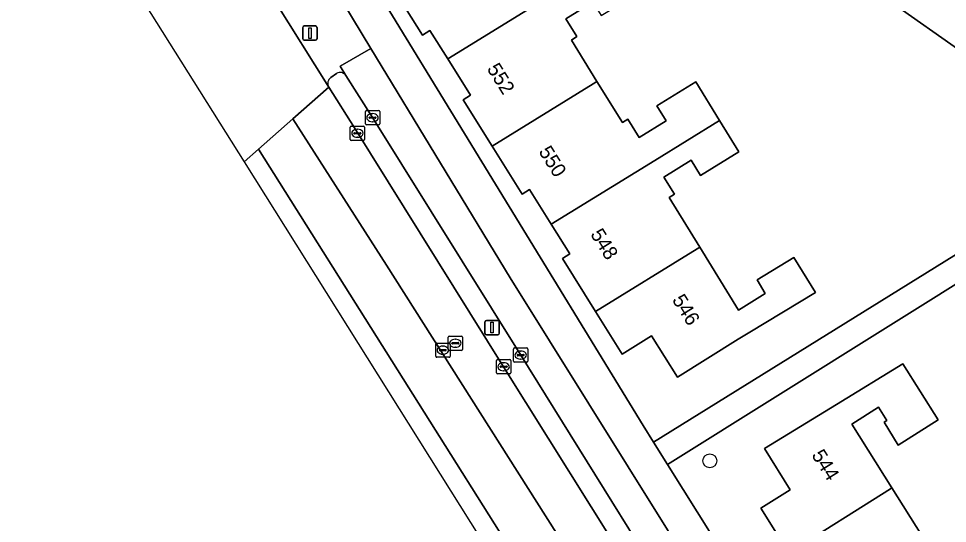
# Model space of a CAD drawing. Extents: x 159664 to 160323, y 385312 to 386115.
# Drawn here: x 159664.3 to 159729.1, y 385837.6 to 385872.8 of the extents above; entities that cross this region are included whole.
import ezdxf

# ---------------------------------------------------------------- set-up
doc = ezdxf.new("R2010")
doc.units = 0
for name, color, linetype in [('IMGEO_Berm_open', 7, 'Continuous'), ('IMGEO_Boom', 7, 'Continuous'), ('IMGEO_Erf', 7, 'Continuous'), ('IMGEO_Fietspad_gesloten', 7, 'Continuous'), ('IMGEO_Fietspad_open', 7, 'Continuous'), ('IMGEO_Kolk', 7, 'Continuous'), ('IMGEO_Lichtmast', 7, 'Continuous'), ('IMGEO_Pand', 7, 'Continuous'), ('IMGEO_Pand_nummerreeks', 7, 'Continuous'), ('IMGEO_Rijbaan_regionaal_gesloten', 7, 'Continuous'), ('IMGEO_Rioolput', 7, 'Continuous'), ('IMGEO_Verkeersregelinstallatiepaal', 7, 'Continuous'), ('IMGEO_Voetpad_open', 7, 'Continuous')]:
    doc.layers.add(name, color=color, linetype=linetype)

msp = doc.modelspace()

# ---------------------------------------------------------------- linework, layer by layer
at = {"layer": 'IMGEO_Berm_open'}
for points in [[(159686.512, 385869.015), (159686.109, 385868.721)], [(159699.356, 385849.333), (159689.016, 385865.92), (159687.159, 385868.865)], [(159685.962, 385868.059), (159687.762, 385865.202), (159698.166, 385848.523), (159707.398, 385833.746), (159719.9, 385813.65), (159720.286, 385813.027), (159720.44, 385812.85)], [(159721.514, 385813.73), (159720.566, 385815.282), (159708.631, 385834.436), (159699.356, 385849.333)]]:
    msp.add_lwpolyline(points, dxfattribs=at)
for centre, radius, start, end in [((159686.39, 385868.311), 0.497, 124.44432, 210.5164), ((159686.751, 385868.576), 0.5, 35.31305, 118.58133)]:
    msp.add_arc(centre, radius, start, end, dxfattribs=at)
at = {"layer": 'IMGEO_Boom'}
msp.add_circle((159712.557, 385841.947), 0.489, dxfattribs=at)
at = {"layer": 'IMGEO_Erf'}
for points in [[(159736.353, 385866.149), (159719.037, 385878.37)], [(159687.283, 385878.163), (159707.902, 385844.411), (159708.629, 385843.25), (159739.153, 385862.198)], [(159711.57, 385868.416), (159713.23, 385865.722), (159714.585, 385863.522), (159711.909, 385861.874), (159711.251, 385862.941), (159709.352, 385861.772), (159710.092, 385860.572), (159709.716, 385860.34), (159711.853, 385856.871), (159714.556, 385852.483), (159716.432, 385853.639), (159715.851, 385854.581), (159718.41, 385856.158), (159719.924, 385853.7), (159715.347, 385850.939), (159714.539, 385850.435), (159710.298, 385847.786), (159708.488, 385850.684), (159706.449, 385849.41), (159704.586, 385852.389), (159702.27, 385856.091), (159702.78, 385856.41), (159701.485, 385858.479), (159699.969, 385860.903), (159699.461, 385860.585), (159697.364, 385863.939), (159695.347, 385867.165), (159695.856, 385867.483), (159694.263, 385870.029), (159693.024, 385872.01), (159692.515, 385871.692), (159690.141, 385875.488)], [(159704.398, 385873.991), (159702.511, 385872.828), (159703.28, 385871.58), (159702.898, 385871.344), (159704.68, 385868.451), (159706.455, 385865.57), (159706.839, 385865.807), (159707.624, 385864.532), (159709.517, 385865.698), (159708.868, 385866.751), (159711.57, 385868.416)], [(159718.061, 385835.526), (159716.118, 385838.631), (159718.175, 385839.916), (159716.363, 385842.815), (159721.394, 385845.894), (159726.034, 385848.734), (159728.503, 385844.802), (159725.712, 385843.049), (159724.715, 385844.637), (159724.924, 385844.769), (159724.34, 385845.699), (159722.462, 385844.52), (159725.268, 385840.05), (159727.349, 385836.736)]]:
    msp.add_lwpolyline(points, dxfattribs=at)
msp.add_lwpolyline([(159749.78, 385845.505), (159747.52, 385845.517), (159747.246, 385845.967), (159748.353, 385847.97), (159740.221, 385860.856), (159709.605, 385841.691), (159725.533, 385816.246), (159727.547, 385813.028), (159757.404, 385831.429), (159757.978, 385832.141), (159757.978, 385832.633)], close=True, dxfattribs=at)
at = {"layer": 'IMGEO_Fietspad_gesloten'}
msp.add_lwpolyline([(159689.016, 385865.92), (159699.356, 385849.333), (159708.631, 385834.436), (159720.566, 385815.282), (159721.514, 385813.73), (159726.241, 385806.163), (159746.799, 385773.289), (159761.349, 385750), (159769.568, 385736.844), (159790.48, 385703.378), (159792.384, 385704.563), (159772.652, 385736.21), (159767.476, 385744.488), (159764.031, 385750), (159753.712, 385766.513), (159748.937, 385774.15), (159728.287, 385807.194), (159723.506, 385814.826), (159723.438, 385814.935), (159698.624, 385854.738), (159688.899, 385870.747), (159686.756, 385869.506), (159687.159, 385868.865)], close=True, dxfattribs=at)
at = {"layer": 'IMGEO_Fietspad_open'}
for points in [[(159687.159, 385868.865), (159686.756, 385869.506), (159688.899, 385870.747), (159685.047, 385877.122)], [(159681.196, 385875.993), (159682.169, 385874.114), (159685.962, 385868.059)], [(159686.109, 385868.721), (159686.512, 385869.015)]]:
    msp.add_lwpolyline(points, dxfattribs=at)
for centre, radius, start, end in [((159686.39, 385868.311), 0.497, 124.44432, 210.5164), ((159686.751, 385868.576), 0.5, 35.31305, 118.58133)]:
    msp.add_arc(centre, radius, start, end, dxfattribs=at)
at = {"layer": 'IMGEO_Kolk'}
for p, q in [((159688.514, 385865.493), (159688.514, 385866.345)), ((159688.589, 385866.419), (159689.441, 385866.419)), ((159688.816, 385865.962), (159689.214, 385865.962)), ((159689.002, 385866.199), (159689.027, 385866.199)), ((159689.515, 385866.345), (159689.515, 385865.493)), ((159687.536, 385865.328), (159688.388, 385865.328)), ((159689.441, 385865.419), (159688.589, 385865.419)), ((159688.773, 385865.913), (159688.773, 385865.925)), ((159689.211, 385865.876), (159688.813, 385865.876)), ((159689.025, 385865.639), (159689, 385865.639)), ((159689.257, 385865.925), (159689.257, 385865.913)), ((159687.461, 385864.402), (159687.461, 385865.254)), ((159687.72, 385864.822), (159687.72, 385864.834)), ((159688.158, 385864.785), (159687.76, 385864.785)), ((159687.763, 385864.871), (159688.161, 385864.871)), ((159687.949, 385865.108), (159687.974, 385865.108)), ((159688.204, 385864.834), (159688.204, 385864.822)), ((159688.462, 385865.254), (159688.462, 385864.402)), ((159688.388, 385864.328), (159687.536, 385864.328)), ((159687.972, 385864.548), (159687.947, 385864.548)), ((159698.854, 385848.907), (159698.854, 385849.759)), ((159698.929, 385849.833), (159699.781, 385849.833)), ((159699.855, 385849.759), (159699.855, 385848.907)), ((159699.113, 385849.327), (159699.113, 385849.339)), ((159699.551, 385849.29), (159699.153, 385849.29)), ((159699.156, 385849.376), (159699.554, 385849.376)), ((159699.342, 385849.613), (159699.367, 385849.613)), ((159699.597, 385849.339), (159699.597, 385849.327)), ((159697.664, 385848.096), (159697.664, 385848.948)), ((159697.739, 385849.022), (159698.591, 385849.022)), ((159697.923, 385848.516), (159697.923, 385848.528)), ((159698.361, 385848.479), (159697.963, 385848.479)), ((159697.966, 385848.565), (159698.364, 385848.565)), ((159698.152, 385848.802), (159698.177, 385848.802)), ((159698.407, 385848.528), (159698.407, 385848.516)), ((159698.665, 385848.948), (159698.665, 385848.096)), ((159699.781, 385848.833), (159698.929, 385848.833)), ((159699.365, 385849.053), (159699.34, 385849.053)), ((159698.591, 385848.022), (159697.739, 385848.022)), ((159698.175, 385848.242), (159698.15, 385848.242))]:
    msp.add_line(p, q, dxfattribs=at)
for points in [[(159688.514, 385865.493), (159688.514, 385866.345)], [(159688.589, 385866.419), (159689.441, 385866.419)], [(159689.515, 385866.345), (159689.515, 385865.493)], [(159687.536, 385865.328), (159688.388, 385865.328)], [(159689.441, 385865.419), (159688.589, 385865.419)], [(159687.461, 385864.402), (159687.461, 385865.254)], [(159688.462, 385865.254), (159688.462, 385864.402)], [(159688.388, 385864.328), (159687.536, 385864.328)], [(159698.854, 385848.907), (159698.854, 385849.759)], [(159698.929, 385849.833), (159699.781, 385849.833)], [(159699.855, 385849.759), (159699.855, 385848.907)], [(159697.664, 385848.096), (159697.664, 385848.948)], [(159697.739, 385849.022), (159698.591, 385849.022)], [(159698.665, 385848.948), (159698.665, 385848.096)], [(159699.781, 385848.833), (159698.929, 385848.833)], [(159698.591, 385848.022), (159697.739, 385848.022)]]:
    msp.add_lwpolyline(points, dxfattribs=at)
for centre, radius, start, end in [((159688.591, 385866.343), 0.0765, 91.55205, 178.44795), ((159688.591, 385866.343), 0.0765, 91.55205, 178.44795), ((159688.813, 385865.922), 0.0403, 85.87752, 175.75265), ((159689.218, 385865.924), 0.0386, 1.73085, 96.63898), ((159689.439, 385866.343), 0.0765, 1.55205, 88.44795), ((159689.439, 385866.343), 0.0765, 1.55205, 88.44795), ((159687.538, 385865.252), 0.0765, 91.55205, 178.44795), ((159687.538, 385865.252), 0.0765, 91.55205, 178.44795), ((159688.386, 385865.252), 0.0765, 1.55205, 88.44795), ((159688.386, 385865.252), 0.0765, 1.55205, 88.44795), ((159688.591, 385865.495), 0.0765, 181.55205, 268.44795), ((159688.591, 385865.495), 0.0765, 181.55205, 268.44795), ((159688.81, 385865.912), 0.0366, 178.93798, 274.71019), ((159689.214, 385865.919), 0.043, 264.86636, 352.45326), ((159689.439, 385865.495), 0.0765, 271.55205, 358.44795), ((159689.439, 385865.495), 0.0765, 271.55205, 358.44795), ((159687.76, 385864.831), 0.0403, 85.87752, 175.75265), ((159687.757, 385864.821), 0.0366, 178.93798, 274.71019), ((159688.161, 385864.828), 0.043, 264.86636, 352.45326), ((159688.165, 385864.833), 0.0386, 1.73085, 96.63898), ((159687.538, 385864.404), 0.0765, 181.55205, 268.44795), ((159687.538, 385864.404), 0.0765, 181.55205, 268.44795), ((159688.386, 385864.404), 0.0765, 271.55205, 358.44795), ((159688.386, 385864.404), 0.0765, 271.55205, 358.44795), ((159698.931, 385849.757), 0.0765, 91.55205, 178.44795), ((159698.931, 385849.757), 0.0765, 91.55205, 178.44795), ((159699.779, 385849.757), 0.0765, 1.55205, 88.44795), ((159699.779, 385849.757), 0.0765, 1.55205, 88.44795), ((159699.153, 385849.336), 0.0403, 85.87752, 175.75265), ((159699.15, 385849.326), 0.0366, 178.93798, 274.71019), ((159699.554, 385849.333), 0.043, 264.86636, 352.45326), ((159699.558, 385849.338), 0.0386, 1.73085, 96.63898), ((159697.741, 385848.946), 0.0765, 91.55205, 178.44795), ((159697.741, 385848.946), 0.0765, 91.55205, 178.44795), ((159697.963, 385848.525), 0.0403, 85.87752, 175.75265), ((159697.96, 385848.515), 0.0366, 178.93798, 274.71019), ((159698.364, 385848.522), 0.043, 264.86636, 352.45326), ((159698.368, 385848.527), 0.0386, 1.73085, 96.63898), ((159698.589, 385848.946), 0.0765, 1.55205, 88.44795), ((159698.589, 385848.946), 0.0765, 1.55205, 88.44795), ((159698.931, 385848.909), 0.0765, 181.55205, 268.44795), ((159698.931, 385848.909), 0.0765, 181.55205, 268.44795), ((159699.779, 385848.909), 0.0765, 271.55205, 358.44795), ((159699.779, 385848.909), 0.0765, 271.55205, 358.44795), ((159697.741, 385848.098), 0.0765, 181.55205, 268.44795), ((159697.741, 385848.098), 0.0765, 181.55205, 268.44795), ((159698.589, 385848.098), 0.0765, 271.55205, 358.44795), ((159698.589, 385848.098), 0.0765, 271.55205, 358.44795)]:
    msp.add_arc(centre, radius, start, end, dxfattribs=at)
for centre, major_axis, ratio, start_param, end_param in [((159689.001, 385865.919), (-0.387, 0.002), 0.722429, 4.712389, 7.853982), ((159689.026, 385865.919), (-0.39, 0.002), 0.717154, 1.570796, 4.712389), ((159687.948, 385864.828), (-0.387, 0.002), 0.722429, 4.712389, 7.853982), ((159687.973, 385864.828), (-0.39, 0.002), 0.717154, 1.570796, 4.712389), ((159699.341, 385849.333), (-0.387, 0.002), 0.722429, 4.712389, 7.853982), ((159699.366, 385849.333), (-0.39, 0.002), 0.717154, 1.570796, 4.712389), ((159698.151, 385848.522), (-0.387, 0.002), 0.722429, 4.712389, 7.853982), ((159698.176, 385848.522), (-0.39, 0.002), 0.717154, 1.570796, 4.712389)]:
    msp.add_ellipse(centre, major_axis=major_axis, ratio=ratio, start_param=start_param, end_param=end_param, dxfattribs=at)
at = {"layer": 'IMGEO_Lichtmast'}
for p, q in [((159696.963, 385851.753), (159697.753, 385851.753)), ((159697.753, 385851.753), (159696.963, 385851.753)), ((159696.863, 385850.853), (159696.863, 385851.653)), ((159696.863, 385851.653), (159696.863, 385850.853)), ((159697.853, 385851.653), (159697.853, 385850.853)), ((159697.853, 385850.853), (159697.853, 385851.653)), ((159697.753, 385850.753), (159696.963, 385850.753)), ((159696.963, 385850.753), (159697.753, 385850.753))]:
    msp.add_line(p, q, dxfattribs=at)
msp.add_lwpolyline([(159697.283, 385851.628), (159697.433, 385851.628), (159697.433, 385850.878), (159697.283, 385850.878), (159697.283, 385851.628)], dxfattribs=at)
for centre, start, end in [((159696.963, 385851.653), 90, 180), ((159696.963, 385851.653), 90, 180), ((159697.753, 385851.653), 0, 90), ((159697.753, 385851.653), 360, 90), ((159696.963, 385850.853), 180, 270), ((159696.963, 385850.853), 180, 270), ((159697.753, 385850.853), 270, 0), ((159697.753, 385850.853), 270, 0)]:
    msp.add_arc(centre, 0.1, start, end, dxfattribs=at)
at = {"layer": 'IMGEO_Pand'}
for points in [[(159701.957, 385877.871), (159702.633, 385876.773), (159700.782, 385875.633), (159700.016, 385876.876), (159699.596, 385876.618), (159697.497, 385880.025), (159697.209, 385879.847), (159690.141, 385875.488), (159692.515, 385871.692), (159693.024, 385872.01), (159694.263, 385870.029), (159701.352, 385874.4), (159706.083, 385877.318), (159704.701, 385879.561)], [(159702.898, 385871.344), (159703.28, 385871.58), (159702.511, 385872.828), (159704.398, 385873.991), (159704.981, 385873.046), (159707.688, 385874.713), (159706.29, 385876.983), (159706.083, 385877.318), (159701.352, 385874.4), (159694.263, 385870.029), (159695.856, 385867.483), (159695.347, 385867.165), (159697.364, 385863.939), (159704.411, 385868.285), (159704.68, 385868.451)], [(159713.23, 385865.722), (159711.57, 385868.416), (159708.868, 385866.751), (159709.517, 385865.698), (159707.624, 385864.532), (159706.839, 385865.807), (159706.455, 385865.57), (159704.68, 385868.451), (159704.411, 385868.285), (159697.364, 385863.939), (159699.461, 385860.585), (159699.969, 385860.903), (159701.485, 385858.479), (159708.714, 385862.937)], [(159708.714, 385862.937), (159701.485, 385858.479), (159702.78, 385856.41), (159702.27, 385856.091), (159704.586, 385852.389), (159711.684, 385856.767), (159711.853, 385856.871), (159709.716, 385860.34), (159710.092, 385860.572), (159709.352, 385861.772), (159711.251, 385862.941), (159711.909, 385861.874), (159714.585, 385863.522), (159713.23, 385865.722)], [(159711.684, 385856.767), (159704.586, 385852.389), (159706.449, 385849.41), (159708.488, 385850.684), (159710.298, 385847.786), (159714.539, 385850.435), (159715.347, 385850.939), (159719.924, 385853.7), (159718.41, 385856.158), (159715.851, 385854.581), (159716.432, 385853.639), (159714.556, 385852.483), (159711.853, 385856.871)], [(159716.363, 385842.815), (159718.175, 385839.916), (159716.118, 385838.631), (159718.061, 385835.526), (159725.165, 385839.985), (159725.268, 385840.05), (159722.462, 385844.52), (159724.34, 385845.699), (159724.924, 385844.769), (159724.715, 385844.637), (159725.712, 385843.049), (159728.503, 385844.802), (159726.034, 385848.734), (159721.394, 385845.894)], [(159725.165, 385839.985), (159718.061, 385835.526), (159720.309, 385831.935), (159720.818, 385832.253), (159722.25, 385829.965), (159729.463, 385834.492), (159733.573, 385837.072), (159732.097, 385839.423), (159729.78, 385837.969), (159730.423, 385836.946), (159728.525, 385835.755), (159727.751, 385836.987), (159727.349, 385836.736), (159725.268, 385840.05)]]:
    msp.add_lwpolyline(points, close=True, dxfattribs=at)
at = {"layer": 'IMGEO_Rijbaan_regionaal_gesloten'}
for points in [[(159673.153, 385891.368), (159672.265, 385892.74), (159664.311, 385887.909), (159680.046, 385862.823)], [(159680.046, 385862.823), (159681.056, 385863.717), (159683.457, 385865.842), (159685.962, 385868.059), (159682.169, 385874.114), (159681.196, 385875.993), (159680.604, 385877.808), (159680.45, 385878.908), (159674.897, 385888.863), (159674.772, 385888.772)], [(159704.448, 385832.81), (159689.98, 385855.614), (159683.457, 385865.842), (159681.056, 385863.717), (159700.472, 385832.883)]]:
    msp.add_lwpolyline(points, dxfattribs=at)
for points in [[(159707.398, 385833.746), (159698.166, 385848.523), (159687.762, 385865.202), (159685.962, 385868.059), (159683.457, 385865.842), (159689.98, 385855.614), (159704.448, 385832.81), (159718.81, 385810.264), (159721.888, 385803.885), (159722.743, 385802.489), (159722.776, 385802.519), (159722.812, 385802.546), (159722.85, 385802.57), (159722.891, 385802.59), (159722.932, 385802.607), (159722.975, 385802.619), (159723.019, 385802.628), (159723.064, 385802.633), (159723.109, 385802.634), (159723.154, 385802.631), (159720.687, 385811.648), (159720.121, 385812.906), (159720.286, 385813.027), (159719.9, 385813.65)], [(159722.474, 385795.185), (159718.071, 385804.138), (159716.049, 385808.25), (159711.375, 385815.569), (159700.472, 385832.883), (159681.056, 385863.717), (159680.046, 385862.823)]]:
    msp.add_lwpolyline(points, close=True, dxfattribs=at)
at = {"layer": 'IMGEO_Rioolput'}
for p, q in [((159694.294, 385849.735), (159694.294, 385850.587)), ((159694.369, 385850.661), (159695.221, 385850.661)), ((159694.782, 385850.441), (159694.807, 385850.441)), ((159695.295, 385850.587), (159695.295, 385849.735)), ((159693.424, 385849.252), (159693.424, 385850.104)), ((159693.499, 385850.178), (159694.351, 385850.178)), ((159693.912, 385849.958), (159693.937, 385849.958)), ((159694.425, 385850.104), (159694.425, 385849.252)), ((159694.553, 385850.155), (159694.553, 385850.167)), ((159694.991, 385850.118), (159694.593, 385850.118)), ((159694.596, 385850.204), (159694.994, 385850.204)), ((159694.805, 385849.881), (159694.78, 385849.881)), ((159695.037, 385850.167), (159695.037, 385850.155)), ((159694.351, 385849.178), (159693.499, 385849.178)), ((159693.683, 385849.672), (159693.683, 385849.684)), ((159694.121, 385849.635), (159693.723, 385849.635)), ((159693.726, 385849.721), (159694.124, 385849.721)), ((159693.935, 385849.398), (159693.91, 385849.398)), ((159694.167, 385849.684), (159694.167, 385849.672)), ((159695.221, 385849.661), (159694.369, 385849.661))]:
    msp.add_line(p, q, dxfattribs=at)
for points in [[(159694.294, 385849.735), (159694.294, 385850.587)], [(159694.369, 385850.661), (159695.221, 385850.661)], [(159695.295, 385850.587), (159695.295, 385849.735)], [(159693.424, 385849.252), (159693.424, 385850.104)], [(159693.499, 385850.178), (159694.351, 385850.178)], [(159694.425, 385850.104), (159694.425, 385849.252)], [(159694.351, 385849.178), (159693.499, 385849.178)], [(159695.221, 385849.661), (159694.369, 385849.661)]]:
    msp.add_lwpolyline(points, dxfattribs=at)
for centre, radius, start, end in [((159694.371, 385850.585), 0.0765, 91.55205, 178.44795), ((159694.371, 385850.585), 0.0765, 91.55205, 178.44795), ((159695.219, 385850.585), 0.0765, 1.55205, 88.44795), ((159695.219, 385850.585), 0.0765, 1.55205, 88.44795), ((159693.501, 385850.102), 0.0765, 91.55205, 178.44795), ((159693.501, 385850.102), 0.0765, 91.55205, 178.44795), ((159694.349, 385850.102), 0.0765, 1.55205, 88.44795), ((159694.349, 385850.102), 0.0765, 1.55205, 88.44795), ((159694.593, 385850.164), 0.0403, 85.87752, 175.75265), ((159694.59, 385850.154), 0.0366, 178.93798, 274.71019), ((159694.994, 385850.161), 0.043, 264.86636, 352.45326), ((159694.998, 385850.166), 0.0386, 1.73085, 96.63898), ((159693.501, 385849.254), 0.0765, 181.55205, 268.44795), ((159693.501, 385849.254), 0.0765, 181.55205, 268.44795), ((159693.723, 385849.681), 0.0403, 85.87752, 175.75265), ((159693.72, 385849.671), 0.0366, 178.93798, 274.71019), ((159694.124, 385849.678), 0.043, 264.86636, 352.45326), ((159694.128, 385849.683), 0.0386, 1.73085, 96.63898), ((159694.371, 385849.737), 0.0765, 181.55205, 268.44795), ((159694.371, 385849.737), 0.0765, 181.55205, 268.44795), ((159694.349, 385849.254), 0.0765, 271.55205, 358.44795), ((159694.349, 385849.254), 0.0765, 271.55205, 358.44795), ((159695.219, 385849.737), 0.0765, 271.55205, 358.44795), ((159695.219, 385849.737), 0.0765, 271.55205, 358.44795)]:
    msp.add_arc(centre, radius, start, end, dxfattribs=at)
for centre, major_axis, ratio, start_param, end_param in [((159694.781, 385850.161), (-0.387, 0.002), 0.722429, 4.712389, 7.853982), ((159694.806, 385850.161), (-0.39, 0.002), 0.717154, 1.570796, 4.712389), ((159693.911, 385849.678), (-0.387, 0.002), 0.722429, 4.712389, 7.853982), ((159693.936, 385849.678), (-0.39, 0.002), 0.717154, 1.570796, 4.712389)]:
    msp.add_ellipse(centre, major_axis=major_axis, ratio=ratio, start_param=start_param, end_param=end_param, dxfattribs=at)
at = {"layer": 'IMGEO_Verkeersregelinstallatiepaal'}
for p, q in [((159684.152, 385871.425), (159684.152, 385872.225)), ((159684.152, 385872.225), (159684.152, 385871.425)), ((159684.252, 385872.325), (159685.042, 385872.325)), ((159685.042, 385872.325), (159684.252, 385872.325)), ((159685.142, 385872.225), (159685.142, 385871.425)), ((159685.142, 385871.425), (159685.142, 385872.225)), ((159685.042, 385871.325), (159684.252, 385871.325)), ((159684.252, 385871.325), (159685.042, 385871.325))]:
    msp.add_line(p, q, dxfattribs=at)
msp.add_lwpolyline([(159684.572, 385872.2), (159684.722, 385872.2), (159684.722, 385871.45), (159684.572, 385871.45), (159684.572, 385872.2)], dxfattribs=at)
for centre, start, end in [((159684.252, 385872.225), 90, 180), ((159684.252, 385872.225), 90, 180), ((159685.042, 385872.225), 0, 90), ((159685.042, 385872.225), 360, 90), ((159684.252, 385871.425), 180, 270), ((159684.252, 385871.425), 180, 270), ((159685.042, 385871.425), 270, 0), ((159685.042, 385871.425), 270, 0)]:
    msp.add_arc(centre, 0.1, start, end, dxfattribs=at)
at = {"layer": 'IMGEO_Voetpad_open'}
for points in [[(159730.384, 385886.363), (159720.352, 385880.122), (159717.531, 385884.658), (159714.464, 385889.586), (159713.115, 385888.758), (159710.707, 385892.683), (159706.962, 385898.821), (159705.781, 385898.08), (159708.4, 385893.787), (159714.134, 385884.61), (159717.594, 385879.636), (159719.037, 385878.37), (159736.353, 385866.149)], [(159725.533, 385816.246), (159709.605, 385841.691), (159708.629, 385843.25), (159707.902, 385844.411), (159687.283, 385878.163), (159685.346, 385881.873), (159684.933, 385880.893), (159684.69, 385880.161), (159684.605, 385879.834), (159684.549, 385879.501), (159684.523, 385879.164), (159684.528, 385878.826), (159684.562, 385878.49), (159684.627, 385878.159), (159684.72, 385877.834), (159684.843, 385877.519), (159684.993, 385877.217), (159685.047, 385877.122), (159688.899, 385870.747), (159698.624, 385854.738), (159723.438, 385814.935)], [(159739.153, 385862.198), (159708.629, 385843.25), (159709.605, 385841.691), (159740.221, 385860.856)]]:
    msp.add_lwpolyline(points, dxfattribs=at)

# ---------------------------------------------------------------- texts
at = {"layer": 'IMGEO_Pand_nummerreeks'}
for s, rotation, p in [('552', 301.95365, (159696.968, 385869.335)), ('550', 302.01567, (159700.577, 385863.554)), ('548', 302.01567, (159704.188, 385857.779)), ('546', 301.99665, (159709.893, 385853.191)), ('544', 301.99996, (159719.627, 385842.349))]:
    msp.add_text(s, height=1, rotation=rotation, dxfattribs=at).set_placement(p)

doc.saveas('drawing.dxf')
